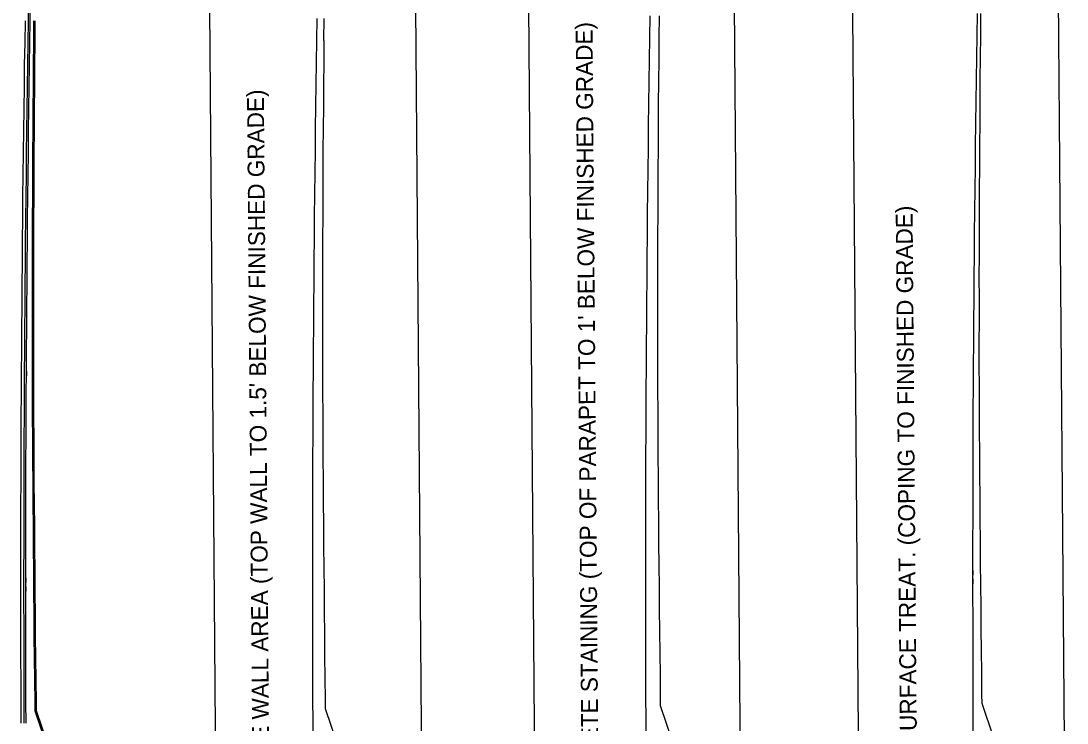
# Model space of a CAD drawing. Extents: x 592966 to 721355, y 141734 to 176528.
# Drawn here: x 594322 to 595512, y 175036 to 175834 of the extents above; entities that cross this region are included whole.
import ezdxf

# ---------------------------------------------------------------- set-up
doc = ezdxf.new("R2010")
doc.units = 0
for name, color, linetype in [('B_CONC', 7, 'Continuous'), ('B_CONC_LT', 7, 'Continuous'), ('B_GROUNDLINE', 7, 'Continuous'), ('B_MISC', 7, 'Continuous')]:
    doc.layers.add(name, color=color, linetype=linetype)

msp = doc.modelspace()

# ---------------------------------------------------------------- linework, layer by layer
at = {"layer": 'B_CONC'}
for p, q in [((594332.2, 175834.3), (594332.6, 175859.3)), ((595409.8, 175842.9), (595409.4, 175817.9)), ((594326.3, 175809.4), (594326.7, 175834.4)), ((594331.8, 175809.3), (594332.2, 175834.3)), ((595037.4, 175840), (595037, 175815)), ((595048, 175815), (595048.3, 175840)), ((594325.9, 175784.5), (594326.3, 175809.4)), ((594331.4, 175784.4), (594331.8, 175809.3)), ((594666.4, 175812), (594666.2, 175787)), ((595037, 175815), (595036.7, 175790.1)), ((595047.8, 175790), (595048, 175815)), ((595409.4, 175817.9), (595409, 175792.9)), ((594325.6, 175759.4), (594325.9, 175784.5)), ((594331.1, 175759.3), (594331.4, 175784.4)), ((594666.2, 175787), (594666, 175762)), ((595036.7, 175790.1), (595036.3, 175765)), ((595047.6, 175765), (595047.8, 175790)), ((595409, 175792.9), (595408.6, 175767.8)), ((594325.2, 175734.4), (594325.6, 175759.4)), ((594330.7, 175734.3), (594331.1, 175759.3)), ((594666, 175762), (594665.8, 175737)), ((595036.3, 175765), (595036, 175740)), ((595047.4, 175740), (595047.6, 175765)), ((595408.6, 175767.8), (595408.3, 175742.8)), ((594665.8, 175737), (594665.6, 175712)), ((595036, 175740), (595035.6, 175715)), ((595047.2, 175715), (595047.4, 175740)), ((595408.3, 175742.8), (595408, 175717.8)), ((594324.9, 175709.4), (594325.2, 175734.4)), ((594330.4, 175709.3), (594330.7, 175734.3)), ((594665.6, 175712), (594665.4, 175687)), ((595035.6, 175715), (595035.3, 175690)), ((595047.1, 175690), (595047.2, 175715)), ((595408, 175717.8), (595407.7, 175692.8)), ((594324.6, 175684.4), (594324.9, 175709.4)), ((594330.1, 175684.3), (594330.4, 175709.3)), ((595035.3, 175690), (595035, 175665)), ((595046.9, 175665), (595047.1, 175690)), ((595407.7, 175692.8), (595407.4, 175667.8)), ((594324.3, 175659.4), (594324.6, 175684.4)), ((594329.8, 175659.3), (594330.1, 175684.3)), ((594665.4, 175687), (594665.3, 175662)), ((595035, 175665), (595034.8, 175640)), ((595046.8, 175640), (595046.9, 175665)), ((595407.4, 175667.8), (595407.1, 175642.8)), ((594324, 175634.4), (594324.3, 175659.4)), ((594329.5, 175634.3), (594329.8, 175659.3)), ((594665.3, 175662), (594665.2, 175637)), ((595034.8, 175640), (595034.5, 175615)), ((595046.7, 175615), (595046.8, 175640)), ((595407.1, 175642.8), (595406.8, 175617.8)), ((594323.8, 175609.4), (594324, 175634.4)), ((594329.3, 175609.3), (594329.5, 175634.3)), ((594665.2, 175637), (594665.1, 175612)), ((595406.8, 175617.8), (595406.6, 175592.8)), ((594323.5, 175584.4), (594323.8, 175609.4)), ((594329, 175584.3), (594329.3, 175609.3)), ((594665.1, 175612), (594665, 175587)), ((595034.5, 175615), (595034.2, 175590)), ((595046.6, 175590), (595046.7, 175615)), ((595406.6, 175592.8), (595406.3, 175567.8)), ((594323.3, 175559.3), (594323.5, 175584.3)), ((594328.8, 175559.3), (594329, 175584.3)), ((594665, 175587), (594664.9, 175562)), ((595034.2, 175590), (595034, 175565)), ((595046.5, 175565), (595046.6, 175590)), ((594323.1, 175534.3), (594323.3, 175559.3)), ((594328.6, 175534.3), (594328.8, 175559.3)), ((594664.9, 175562), (594664.9, 175537)), ((595034, 175565), (595033.8, 175540)), ((595046.5, 175540), (595046.5, 175565)), ((595406.3, 175567.8), (595406.1, 175542.8)), ((594322.9, 175509.3), (594323.1, 175534.3)), ((594328.4, 175509.3), (594328.6, 175534.3)), ((594664.9, 175537), (594664.9, 175512)), ((595033.8, 175540), (595033.6, 175515)), ((595046.5, 175515), (595046.5, 175540)), ((595406.1, 175542.8), (595405.9, 175517.8)), ((594322.7, 175484.3), (594322.9, 175509.3)), ((594328.2, 175484.3), (594328.4, 175509.3)), ((594664.9, 175512), (594664.9, 175487)), ((595033.6, 175515), (595033.4, 175490)), ((595046.5, 175490), (595046.5, 175515)), ((595405.9, 175517.8), (595405.7, 175492.8)), ((594664.9, 175487), (594664.9, 175462)), ((595033.4, 175490), (595033.2, 175465)), ((595046.5, 175465), (595046.5, 175490)), ((595405.7, 175492.8), (595405.6, 175467.8)), ((594322.5, 175459.3), (594322.7, 175484.3)), ((594328, 175459.3), (594328.2, 175484.3)), ((594664.9, 175462), (594664.9, 175437)), ((595033.2, 175465), (595033.1, 175440)), ((595046.5, 175440), (595046.5, 175465)), ((595405.6, 175467.8), (595405.4, 175442.8)), ((594322.3, 175434.3), (594322.5, 175459.3)), ((594327.8, 175434.3), (594328, 175459.3)), ((595033.1, 175440), (595032.9, 175415)), ((595046.6, 175415), (595046.5, 175440)), ((595405.4, 175442.8), (595405.3, 175417.8)), ((594322.2, 175409.3), (594322.3, 175434.3)), ((594327.7, 175409.3), (594327.8, 175434.3)), ((594664.9, 175437), (594665, 175412)), ((595032.9, 175414.9), (595032.8, 175389.9)), ((595046.7, 175390), (595046.6, 175415)), ((595405.3, 175417.8), (595405.1, 175392.8)), ((594322.1, 175384.3), (594322.2, 175409.3)), ((594327.6, 175384.3), (594327.7, 175409.3)), ((594665, 175412), (594665.1, 175387)), ((595032.8, 175389.9), (595032.7, 175364.9)), ((595046.8, 175365), (595046.7, 175390)), ((595405.1, 175392.8), (595405, 175367.8)), ((594322, 175359.3), (594322.1, 175384.3)), ((594327.5, 175359.3), (594327.6, 175384.3)), ((594665.1, 175387), (594665.2, 175362)), ((595405, 175367.8), (595404.9, 175342.8)), ((594321.9, 175334.3), (594322, 175359.3)), ((594327.4, 175334.3), (594327.5, 175359.3)), ((594665.2, 175362), (594665.3, 175337)), ((595032.7, 175364.9), (595032.6, 175339.9)), ((595046.9, 175340), (595046.8, 175365)), ((595404.9, 175342.8), (595404.9, 175317.8)), ((594321.8, 175309.3), (594321.9, 175334.3)), ((594327.3, 175309.3), (594327.4, 175334.3)), ((594665.3, 175337), (594665.5, 175312)), ((595032.6, 175339.9), (595032.5, 175314.9)), ((595047.1, 175315), (595046.9, 175340)), ((594321.7, 175284.3), (594321.8, 175309.3)), ((594327.2, 175284.3), (594327.3, 175309.3)), ((594665.5, 175312), (594665.7, 175287)), ((595032.5, 175314.9), (595032.5, 175289.9)), ((595047.3, 175290), (595047.1, 175315)), ((595404.9, 175317.8), (595404.8, 175292.8)), ((594321.7, 175259.3), (594321.7, 175284.3)), ((594327.2, 175259.3), (594327.2, 175284.3)), ((594665.7, 175287), (594665.9, 175262)), ((595032.5, 175289.9), (595032.4, 175264.9)), ((595047.5, 175265), (595047.3, 175290)), ((595404.8, 175292.8), (595404.8, 175267.8)), ((594321.7, 175234.3), (594321.7, 175259.3)), ((594327.2, 175234.3), (594327.2, 175259.3)), ((594665.9, 175262), (594666.1, 175237)), ((595032.4, 175264.9), (595032.4, 175239.9)), ((595047.7, 175240), (595047.5, 175265)), ((595404.8, 175267.8), (595404.7, 175242.8)), ((594666.1, 175237), (594666.3, 175212)), ((595032.4, 175239.9), (595032.4, 175214.9)), ((595048, 175215), (595047.7, 175240)), ((595404.7, 175242.8), (595404.7, 175217.8)), ((594321.6, 175209.3), (594321.7, 175234.3)), ((594327.1, 175209.3), (594327.2, 175234.3)), ((594666.3, 175212), (594666.6, 175187)), ((595032.4, 175214.9), (595032.4, 175189.9)), ((595048.2, 175190), (595048, 175215)), ((595404.7, 175217.8), (595404.7, 175192.8)), ((594321.6, 175184.3), (594321.6, 175209.3)), ((594327.1, 175184.3), (594327.1, 175209.3)), ((595032.4, 175189.9), (595032.4, 175139.9)), ((595048.4, 175165), (595048.2, 175190)), ((595404.7, 175192.8), (595404.8, 175142.8)), ((594321.7, 175134.3), (594321.6, 175184.3)), ((594327.2, 175134.3), (594327.1, 175184.3)), ((594666.6, 175187), (594666.8, 175162)), ((595048.7, 175140), (595048.4, 175165)), ((594666.8, 175162), (594667, 175137)), ((595032.4, 175139.9), (595032.5, 175114.9)), ((595049, 175115), (595048.7, 175140)), ((595404.8, 175142.8), (595404.8, 175117.8)), ((594321.7, 175109.3), (594321.7, 175134.3)), ((594327.2, 175109.3), (594327.2, 175134.3)), ((594667, 175137), (594667.3, 175112)), ((595404.8, 175117.8), (595404.9, 175092.8)), ((594321.8, 175084.3), (594321.7, 175109.3)), ((594327.3, 175084.3), (594327.2, 175109.3)), ((594667.3, 175112), (594667.6, 175087)), ((595032.5, 175114.9), (595032.5, 175089.9)), ((595049.3, 175090), (595049, 175115)), ((595404.9, 175092.8), (595404.9, 175067.8)), ((594321.9, 175059.3), (594321.8, 175084.3)), ((594327.4, 175059.3), (594327.3, 175084.3)), ((594667.6, 175087), (594667.8, 175062)), ((595032.5, 175089.9), (595032.6, 175064.9)), ((595049.5, 175065), (595049.3, 175090)), ((594322, 175035.5), (594321.9, 175059.3)), ((594327.5, 175035.5), (594327.4, 175059.3)), ((594667.8, 175062), (594667.9, 175052.2)), ((595032.6, 175064.9), (595032.7, 175041.1)), ((595049.5, 175054.7), (595049.5, 175065)), ((595404.9, 175067.8), (595405, 175044.1)), ((594667.9, 175052.2), (594681.3, 175013.1)), ((595062.9, 175015.9), (595049.5, 175055)), ((595032.7, 175041.1), (595032.8, 175022.1)), ((595405, 175044.1), (595405.1, 175025.1))]:
    msp.add_line(p, q, dxfattribs=at)
for points in [[(594546.6, 174596.6), (594531.3, 176523.2), (594765.2, 176525.1), (594780.4, 174598.5)], [(594909.5, 174599.5), (594894.2, 176526.1), (595128.1, 176528), (595143.3, 174601.3)], [(595278.3, 174591.1), (595263.1, 176517.7), (595496.9, 176519.5), (595512.2, 174592.9)]]:
    msp.add_lwpolyline(points, close=True, dxfattribs=at)
for points in [[(594330.2, 175834.3), (594330.6, 175859.4)], [(595413.9, 175817.9), (595414.1, 175842.9)], [(594329.8, 175809.3), (594330.2, 175834.3)], [(594658.4, 175811.9), (594658.8, 175837)], [(594329.4, 175784.4), (594329.8, 175809.3)], [(594658.1, 175787), (594658.4, 175811.9)], [(595413.6, 175792.9), (595413.9, 175817.9)], [(594329.1, 175759.3), (594329.4, 175784.4)], [(594657.7, 175761.9), (594658.1, 175787)], [(595413.4, 175767.9), (595413.6, 175792.9)], [(594328.7, 175734.3), (594329.1, 175759.3)], [(594657.4, 175736.9), (594657.7, 175761.9)], [(595413.2, 175742.9), (595413.4, 175767.9)], [(594657, 175711.9), (594657.4, 175736.9)], [(595413.1, 175717.9), (595413.2, 175742.9)], [(594328.4, 175709.3), (594328.7, 175734.3)], [(594656.7, 175686.9), (594657, 175711.9)], [(595412.9, 175692.9), (595413.1, 175717.9)], [(594328.1, 175684.3), (594328.4, 175709.3)], [(595412.8, 175667.9), (595412.9, 175692.9)], [(594327.8, 175659.3), (594328.1, 175684.3)], [(594656.4, 175661.9), (594656.7, 175686.9)], [(595412.6, 175642.9), (595412.8, 175667.9)], [(594327.5, 175634.3), (594327.8, 175659.3)], [(594656.1, 175636.9), (594656.4, 175661.9)], [(595412.5, 175617.9), (595412.6, 175642.9)], [(594327.3, 175609.3), (594327.5, 175634.3)], [(594655.9, 175611.9), (594656.1, 175636.9)], [(595412.4, 175592.9), (595412.5, 175617.9)], [(594327, 175584.3), (594327.3, 175609.3)], [(594655.6, 175586.9), (594655.9, 175611.9)], [(595412.4, 175567.9), (595412.4, 175592.9)], [(594326.8, 175559.3), (594327, 175584.3)], [(594655.4, 175561.9), (594655.6, 175586.9)], [(594326.6, 175534.3), (594326.8, 175559.3)], [(594655.2, 175536.9), (594655.4, 175561.9)], [(595412.3, 175542.9), (595412.4, 175567.9)], [(594326.4, 175509.3), (594326.6, 175534.3)], [(594655, 175511.9), (594655.2, 175536.9)], [(595412.4, 175517.9), (595412.3, 175542.9)], [(594326.2, 175484.3), (594326.4, 175509.3)], [(594654.8, 175486.9), (594655, 175511.9)], [(595412.4, 175492.9), (595412.4, 175517.9)], [(594654.6, 175461.9), (594654.8, 175486.9)], [(595412.3, 175467.9), (595412.4, 175492.9)], [(594326, 175459.3), (594326.2, 175484.3)], [(594654.5, 175436.9), (594654.6, 175461.9)], [(595412.3, 175442.9), (595412.3, 175467.9)], [(594325.8, 175434.3), (594326, 175459.3)], [(595412.4, 175417.9), (595412.3, 175442.9)], [(594325.7, 175409.3), (594325.8, 175434.3)], [(594654.3, 175411.9), (594654.5, 175436.9)], [(595412.6, 175392.9), (595412.4, 175417.9)], [(594325.6, 175384.3), (594325.7, 175409.3)], [(594654.2, 175386.9), (594654.3, 175411.9)], [(595412.7, 175367.9), (595412.6, 175392.9)], [(594325.5, 175359.3), (594325.6, 175384.3)], [(594654.1, 175361.9), (594654.2, 175386.9)], [(595412.8, 175342.9), (595412.7, 175367.9)], [(594325.4, 175334.3), (594325.5, 175359.3)], [(594654, 175336.9), (594654.1, 175361.9)], [(595412.9, 175317.9), (595412.8, 175342.9)], [(594325.3, 175309.3), (594325.4, 175334.3)], [(594653.9, 175311.9), (594654, 175336.9)], [(594325.2, 175284.3), (594325.3, 175309.3)], [(594653.9, 175286.9), (594653.9, 175311.9)], [(595413.1, 175292.9), (595412.9, 175317.9)], [(594325.2, 175259.3), (594325.2, 175284.3)], [(594653.8, 175261.9), (594653.9, 175286.9)], [(595413.3, 175267.9), (595413.1, 175292.9)], [(594325.2, 175234.3), (594325.2, 175259.3)], [(594653.8, 175236.9), (594653.8, 175261.9)], [(595413.5, 175242.9), (595413.3, 175267.9)], [(594653.8, 175211.9), (594653.8, 175236.9)], [(595413.8, 175217.9), (595413.5, 175242.9)], [(594325.1, 175209.3), (594325.2, 175234.3)], [(594653.8, 175186.9), (594653.8, 175211.9)], [(595414, 175192.9), (595413.8, 175217.9)], [(594325.1, 175184.3), (594325.1, 175209.3)], [(595414.3, 175167.9), (595414, 175192.9)], [(594325.2, 175134.3), (594325.1, 175184.3)], [(594653.8, 175136.9), (594653.8, 175186.9)], [(595414.5, 175142.9), (595414.3, 175167.9)], [(595414.8, 175117.9), (595414.5, 175142.9)], [(594325.2, 175109.3), (594325.2, 175134.3)], [(594653.9, 175111.9), (594653.8, 175136.9)], [(595415.1, 175092.9), (595414.8, 175117.9)], [(594325.3, 175084.3), (594325.2, 175109.3)], [(594653.9, 175086.9), (594653.9, 175111.9)], [(595415.3, 175067.9), (595415.1, 175092.9)], [(594325.4, 175059.3), (594325.3, 175084.3)], [(594654, 175061.9), (594653.9, 175086.9)], [(594325.5, 175035.5), (594325.4, 175059.3)], [(594654.1, 175038.1), (594654, 175061.9)], [(595428.8, 175018.5), (595415.4, 175057.6)], [(594654.2, 175019.1), (594654.1, 175038.1)]]:
    msp.add_lwpolyline(points, dxfattribs=at)
at = {"layer": 'B_CONC_LT'}
for p, q in [((595405.4, 175444.1), (595405.4, 175439.1)), ((594327.8, 175435.5), (594327.9, 175430.5)), ((594327.2, 175200.5), (594327.2, 175195.5)), ((595404.8, 175209.1), (595404.8, 175204.1)), ((595404.8, 175199.1), (595404.9, 175194.1)), ((594327.3, 175190.5), (594327.3, 175185.5))]:
    msp.add_line(p, q, dxfattribs=at)
at = {"layer": 'B_GROUNDLINE'}
for points in [[(594336.3, 175809.4), (594336.5, 175834.4)], [(594336.1, 175784.4), (594336.3, 175809.4)], [(594335.9, 175759.4), (594336.1, 175784.4)], [(594335.7, 175734.4), (594335.9, 175759.4)], [(594335.5, 175709.4), (594335.7, 175734.4)], [(594335.3, 175684.4), (594335.5, 175709.4)], [(594335.2, 175659.4), (594335.3, 175684.4)], [(594335.1, 175634.4), (594335.2, 175659.4)], [(594334.9, 175609.4), (594335.1, 175634.4)], [(594334.8, 175584.4), (594334.9, 175609.4)], [(594334.8, 175559.4), (594334.8, 175584.4)], [(594334.8, 175534.4), (594334.8, 175559.4)], [(594334.8, 175509.4), (594334.8, 175534.4)], [(594334.8, 175484.4), (594334.8, 175509.4)], [(594334.8, 175459.4), (594334.8, 175484.4)], [(594334.8, 175434.4), (594334.8, 175459.4)], [(594334.9, 175409.4), (594334.8, 175434.4)], [(594335, 175384.4), (594334.9, 175409.4)], [(594335.1, 175359.4), (594335, 175384.4)], [(594335.2, 175334.4), (594335.1, 175359.4)], [(594335.4, 175309.4), (594335.2, 175334.4)], [(594335.6, 175284.4), (594335.4, 175309.4)], [(594335.8, 175259.4), (594335.6, 175284.4)], [(594336, 175234.4), (594335.8, 175259.4)], [(594336.2, 175209.4), (594336, 175234.4)], [(594336.5, 175184.4), (594336.2, 175209.4)], [(594336.7, 175159.4), (594336.5, 175184.4)], [(594336.9, 175134.4), (594336.7, 175159.4)], [(594337.2, 175109.4), (594336.9, 175134.4)], [(594337.5, 175084.4), (594337.2, 175109.4)], [(594337.7, 175059.4), (594337.5, 175084.4)], [(594337.8, 175049.1), (594337.7, 175059.4)], [(595415.4, 175057.6), (595415.3, 175067.9)], [(594351.2, 175009.9), (594337.8, 175049.1)]]:
    msp.add_lwpolyline(points, dxfattribs=at)
at = {"layer": 'B_MISC'}
for p, q in [((594337.8, 175809.4), (594338, 175834.4)), ((594666.4, 175812), (594666.6, 175837)), ((594337.6, 175784.3), (594337.8, 175809.4)), ((594337.4, 175759.4), (594337.6, 175784.4)), ((594337.2, 175734.3), (594337.4, 175759.4)), ((594337, 175709.3), (594337.2, 175734.4)), ((594336.8, 175684.3), (594337, 175709.3)), ((594336.7, 175659.3), (594336.8, 175684.4)), ((594336.6, 175634.3), (594336.7, 175659.3)), ((594336.4, 175609.4), (594336.6, 175634.4)), ((594336.3, 175584.3), (594336.4, 175609.4)), ((594336.3, 175559.4), (594336.3, 175584.4)), ((594336.3, 175534.4), (594336.3, 175559.4)), ((594336.3, 175509.4), (594336.3, 175534.4)), ((594336.3, 175484.4), (594336.3, 175509.4)), ((594336.3, 175459.4), (594336.3, 175484.4)), ((594336.3, 175434.4), (594336.3, 175459.4)), ((594336.4, 175409.4), (594336.3, 175434.4)), ((594336.5, 175384.4), (594336.4, 175409.4)), ((594336.6, 175359.4), (594336.5, 175384.4)), ((594336.7, 175334.4), (594336.6, 175359.4)), ((594336.9, 175309.4), (594336.7, 175334.4)), ((594337.1, 175284.4), (594336.9, 175309.4)), ((594337.3, 175259.4), (594337.1, 175284.4)), ((594337.5, 175234.4), (594337.3, 175259.4)), ((594337.7, 175209.4), (594337.5, 175234.4)), ((594338, 175184.4), (594337.7, 175209.4)), ((594338.2, 175159.4), (594338, 175184.4)), ((594338.4, 175134.4), (594338.2, 175159.4)), ((594338.7, 175109.4), (594338.4, 175134.4)), ((594339, 175084.4), (594338.7, 175109.4)), ((594339.2, 175059.4), (594339, 175084.4)), ((594339.3, 175049.6), (594339.2, 175059.4)), ((594352.7, 175010.5), (594339.3, 175049.6))]:
    msp.add_line(p, q, dxfattribs=at)

# ---------------------------------------------------------------- texts
at = {"layer": 'B_CONC'}
for s, p in [("CONCRETE STAINING (TOP OF PARAPET TO 1' BELOW FINISHED GRADE)", (594979.3, 174919.6)), ("MSE WALL AREA (TOP WALL TO 1.5' BELOW FINISHED GRADE)", (594604.3, 174976.9)), ('ARCH. SURFACE TREAT. (COPING TO FINISHED GRADE)', (595341.9, 174922.5))]:
    msp.add_text(s, height=19.2, rotation=90.4539, dxfattribs=at).set_placement(p)

doc.saveas('drawing.dxf')
